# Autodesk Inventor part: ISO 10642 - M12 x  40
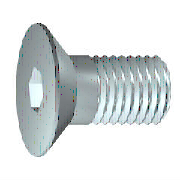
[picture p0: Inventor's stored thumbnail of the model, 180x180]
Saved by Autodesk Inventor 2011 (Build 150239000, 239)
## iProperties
IsCustomPart: 0
Created: 2010-02
Part Number: ISO 10642 - M12 x  40
Material: Steel
Description: Hexagon Socket Countersunk Head Screw-1 - Product grade A
Document SubType Name: Modeling
Standard: ISO 10642
Designer: 129877
Standard Revision: Second edition 2004-03-01
Standards Organization: ISO
Language: en-US
Size Designation: M12 x  40
Categories: <MemberInstance><Categories><Category DisplayName="Fasteners" InternalName="e4da775c-781d-43d5-af7c-5136215cf5a6" Mnemonic="FSTN"><Category DisplayName="Bolts"
Density: 7.85 g/cm^3
Mass: 43.1531 g
Surface Area: 24.6443 cm^2
Volume: 5.49721 cm^3
Author: 129877
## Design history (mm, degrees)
body "Solid1"
workplane "Work Plane1"
revolve "Body" stored, may be unused: angle "d13" = 90 deg
sketch "Sketch2"
  geometry: L1 (0, -16.184)-(0, 16.184) reference; L2 (-16.184, 0)-(16.184, 0) reference; L3 (4.619, 0)-(2.309, -4); L4 (2.309, -4)-(-2.309, -4); L5 (-2.309, -4)-(-4.619, 0); L6 (-4.619, 0)-(-2.309, 4); L7 (-2.309, 4)-(2.309, 4); L8 (2.309, 4)-(4.619, 0); A1 r 4.619 centre (0, 0) between (0, 4.619) and (4.619, 0) reference; 2 further points
  constraints: 12 end point, 2 coincident, 2 point on circle, 2 point on line, 12 other
extrude "Slot" join sketch "Sketch2" taper "d14" = 0 deg; stored distance "d30" = 10
feature "Thread" dims "d15" = 26.5 (= GEL), "d16" = 0
chamfer "Chamfer1" distance "d17" = 1.07354 (= -0.5 x SPD + 0.5 x GD); stored, may be unused: second distance "d18" = 1.07354 (= GUL), angle "d39" = 45 deg
sketch "Sketch1"
  geometry: L1 (40, 0)-(40, 6); L2 (40, 6)-(13.5, 6); L3 (13.5, 6)-(12.426, 6); L4 (0, 11.56)-(0, 4.619); L5 (0, 4.619)-(5.19, 4.619); L6 (5.19, 4.619)-(7.857, 0); L7 (7.857, 0)-(40, 0); L8 (0, 11.56)-(1.88, 11.56); L9 (1.88, 11.56)-(7.44, 6); L10 (12.426, 6)-(7.44, 6); L11 (13.5, 6)-(7.44, 6); L12 (7.44, 6)-(7.44, 6); L13 (-8, 0)-(48, 0) reference; L14 (0, -2.312)-(0, 13.872) reference
  constraints: 24 end point, 4 collinear, 3 parallel
  dimensions: "d0" = 40 distance between parallel lines of L4 L1 (= NLG); "d1" = 26.5 distance from line of L2.end L1 (= GEL); "d2" = 5.19 distance from line of L5.end L4 (= INTI); "d3" = 12 diameter of L2 L7 (= GD); "d6" = 7.44 distance from line of L9.end L4 (= KOH); "d7" = 45 deg angle of L9 L7 (= 0.5 x SEWI); "d8" = 9.2376 diameter of L5 L7 (= 1.1547 x SW); "d9" = 60 deg angle of L6 L7; "d10" = 23.12 diameter of L8 L7 (= KOD); "d11" = 12 diameter of L10 L7 (= BDM); "d12" = 1.07354 distance of L3.end L2.end (= GAL)
other parameters: "NLG" = 40 [user parameter; used in 1 equation term], "INTI" = 5.19 [user parameter; used in 1 equation term], "GEL" = 26.5 [user parameter; used in 2 equation terms], "GAL" = 1.07354 (= 0.61345 x PTC) [user parameter; used in 1 equation term], "KOH" = 7.44 [user parameter; used in 1 equation term], "KOD" = 23.12 [user parameter; used in 1 equation term], "GUL" = 1.07354 (= 0.61345 x PTC) [user parameter; used in 1 equation term], "SPD" = 9.85293 (= NND - 1.2269 x PTC) [user parameter; used in 1 equation term], "BDM" = 12 (= NND) [user parameter; used in 1 equation term], "GD" = 12 (= NND) [user parameter; used in 2 equation terms], "SEWI" = 90 deg [user parameter; used in 1 equation term], "d20" = 0, "SW" = 8 [user parameter; used in 1 equation term], "d43" = 0, "d44" = 0, "TOA" = 30 deg [user parameter], "GD1" = 9.85293 (= THREADDIA - 1.2269 x PTC) [user parameter], "EPV" = 13.44 [user parameter], "THREADDIA" = 12 [user parameter; used in 1 equation term], "TPU" = 5.71429 (computed from PTC) [user parameter], "PTC" = 1.75 [user parameter; used in 5 equation terms], "NND" = 12 [user parameter; used in 3 equation terms], "E0" = 9.24 [user parameter], "THREADDESC" = 12.345 [user parameter]
